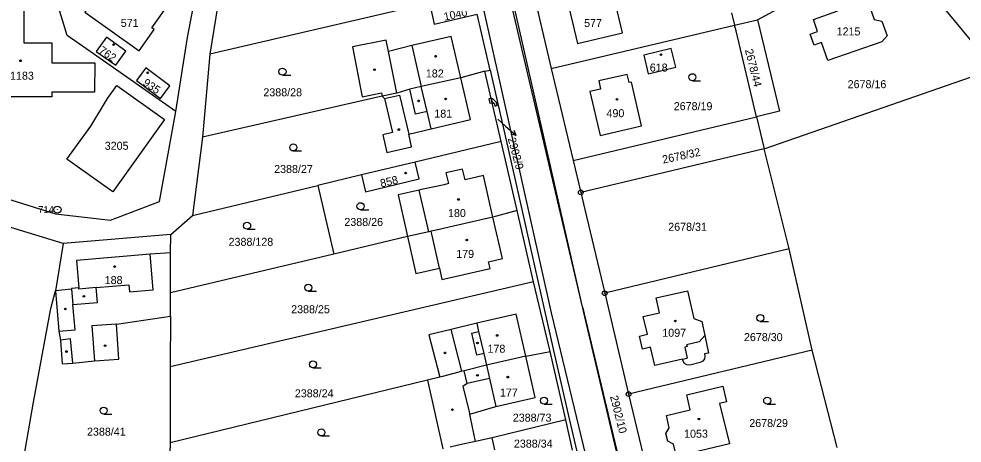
# Model space of a CAD drawing. Extents: x -758836 to -757729, y -1175316 to -1174366.
# Drawn here: x -758454.3 to -758254, y -1175027 to -1174936.9 of the extents above; entities that cross this region are included whole.
import ezdxf

# ---------------------------------------------------------------- set-up
doc = ezdxf.new("R2010")
doc.units = 0
for name, color, linetype in [('Hranice parcel', 7, 'Continuous'), ('Parcelní čísla', 7, 'Continuous'), ('Pop  PČ popisy', 7, 'Continuous'), ('Vnitřní kresba', 7, 'Continuous'), ('Věcná břemena k části', 7, 'Continuous'), ('Značky bodu BP', 7, 'Continuous'), ('Značky budov', 7, 'Continuous'), ('Značky kultur', 7, 'Continuous')]:
    doc.layers.add(name, color=color, linetype=linetype)

msp = doc.modelspace()

# ---------------------------------------------------------------- linework, layer by layer
at = {"layer": 'Hranice parcel'}
for p, q in [((-758345.78, -1174928.06), (-758341.26, -1174947.41)), ((-758357.99, -1174931.4), (-758413.76, -1174944.36)), ((-758354.19, -1174947.79), (-758356.95, -1174935.89)), ((-758302.92, -1174935.57), (-758302.28, -1174938.23)), ((-758302.28, -1174938.23), (-758297.41, -1174937.08)), ((-758341.26, -1174947.41), (-758302.28, -1174938.23)), ((-758413.76, -1174944.36), (-758415.31, -1174962.01)), ((-758355.36, -1174948.01), (-758360.44, -1174949.43)), ((-758355.36, -1174948.01), (-758354.19, -1174947.79)), ((-758351.86, -1174962.91), (-758355.36, -1174948.01)), ((-758341.26, -1174947.41), (-758336.59, -1174966.93)), ((-758377.14, -1174953.27), (-758415.31, -1174962.01)), ((-758336.59, -1174966.93), (-758297.64, -1174957.65)), ((-758297.64, -1174957.65), (-758296.01, -1174964.46)), ((-758415.31, -1174962.01), (-758417.43, -1174978.6)), ((-758351.86, -1174962.91), (-758370.14, -1174967.28)), ((-758348.51, -1174977.6), (-758351.86, -1174962.91)), ((-758296.01, -1174964.46), (-758334.97, -1174973.74)), ((-758290.72, -1174985.7), (-758296.01, -1174964.46)), ((-758336.59, -1174966.93), (-758334.97, -1174973.74)), ((-758370.14, -1174967.28), (-758381.55, -1174970.01)), ((-758360.06, -1174968.77), (-758363.6, -1174969.56)), ((-758381.55, -1174970.01), (-758390.82, -1174972.23)), ((-758417.43, -1174978.6), (-758390.82, -1174972.23)), ((-758390.82, -1174972.23), (-758387.4, -1174986.81)), ((-758422.04, -1174982.66), (-758417.43, -1174978.6)), ((-758348.51, -1174977.6), (-758353.61, -1174978.97)), ((-758345.02, -1174992.7), (-758348.51, -1174977.6)), ((-758422.04, -1174982.66), (-758444.91, -1174984.58)), ((-758371.77, -1174983.1), (-758387.4, -1174986.81)), ((-758444.91, -1174984.58), (-758446.54, -1174994.59)), ((-758387.4, -1174986.81), (-758422.1, -1174995.06)), ((-758290.72, -1174985.7), (-758329.89, -1174995.14)), ((-758285.8, -1175007.25), (-758290.72, -1174985.7)), ((-758345.02, -1174992.7), (-758422.18, -1175010.77)), ((-758341.49, -1175007.47), (-758345.02, -1174992.7)), ((-758422.13, -1175000.03), (-758422.1, -1174995.06)), ((-758329.89, -1174995.14), (-758324.8, -1175016.55)), ((-758422.13, -1175000.03), (-758422.18, -1175010.77)), ((-758346.66, -1175008.52), (-758341.49, -1175007.47)), ((-758338.16, -1175021.98), (-758341.49, -1175007.47)), ((-758285.8, -1175007.25), (-758324.8, -1175016.55)), ((-758280.48, -1175027.85), (-758285.8, -1175007.25)), ((-758422.18, -1175010.77), (-758422.16, -1175026.87)), ((-758364.93, -1175012.95), (-758367.53, -1175013.58)), ((-758367.53, -1175013.58), (-758422.16, -1175026.87)), ((-758367.53, -1175013.58), (-758364.25, -1175028.17)), ((-758324.8, -1175016.55), (-758319.72, -1175037.95)), ((-758336.71, -1175028.44), (-758338.16, -1175021.98)), ((-758422.16, -1175026.87), (-758422.36, -1175032.02))]:
    msp.add_line(p, q, dxfattribs=at)
for points in [[(-758297.14, -1175157.07), (-758301.82, -1175137.17), (-758334.58, -1174998.03), (-758360.35, -1174888.27), (-758361.81, -1174882.07)], [(-758420.99, -1174956.58), (-758418.47, -1174940.81), (-758410.71, -1174900.14)], [(-758297.41, -1174937.08), (-758278.62, -1174926.8), (-758276.96, -1174925.54), (-758269.21, -1174920.77)], [(-758296.01, -1174964.46), (-758247.07, -1174947.51), (-758269.21, -1174920.77)], [(-758410.64, -1174925.24), (-758410.72, -1174925.53), (-758413.76, -1174944.36)], [(-758420.99, -1174956.58), (-758438.47, -1174944.3), (-758444.03, -1174940.39), (-758448.12, -1174927.13)], [(-758422.41, -1174933.59), (-758429.78, -1174928.35), (-758432.94, -1174932.84), (-758436.6, -1174930.22), (-758440.31, -1174935.48), (-758434.92, -1174939.3), (-758428.76, -1174943.67), (-758425.55, -1174939.12), (-758426.06, -1174938.77), (-758422.41, -1174933.59)], [(-758326.1, -1174939.86), (-758328.65, -1174929.09), (-758330.65, -1174929.56), (-758331.04, -1174927.9), (-758337.01, -1174929.38), (-758336.63, -1174930.98), (-758338.22, -1174931.36), (-758335.63, -1174942.14), (-758326.1, -1174939.86)], [(-758460.27, -1174942), (-758460.27, -1174929.65), (-758453.25, -1174929.64), (-758453.27, -1174941.98), (-758447.28, -1174941.99), (-758447.29, -1174946.22), (-758438.2, -1174946.25), (-758438.23, -1174952.48), (-758447.31, -1174952.45), (-758447.31, -1174953.41), (-758466.25, -1174953.42), (-758466.22, -1174942), (-758460.27, -1174942)], [(-758271, -1174941.74), (-758282.48, -1174945.75), (-758283.82, -1174941.92), (-758285.42, -1174942.48), (-758286.25, -1174940.1), (-758284.66, -1174939.55), (-758285.55, -1174937), (-758280.36, -1174935.18), (-758281.59, -1174931.68), (-758275.27, -1174929.47), (-758272.62, -1174937.05), (-758271.01, -1174937.37), (-758269.92, -1174940.49), (-758271, -1174941.74)], [(-758357.84, -1174932.05), (-758366.97, -1174934.14), (-758366.08, -1174938), (-758356.95, -1174935.89)], [(-758297.41, -1174937.08), (-758292.77, -1174956.49), (-758297.64, -1174957.65)], [(-758297.64, -1174957.65), (-758301.99, -1174939.46), (-758302.28, -1174938.23)], [(-758431.62, -1174943.73), (-758435.72, -1174940.79), (-758437.89, -1174943.84), (-758433.72, -1174946.69), (-758431.62, -1174943.73)], [(-758360.44, -1174949.43), (-758362.5, -1174940.61), (-758370.87, -1174942.56), (-758375.84, -1174943.78), (-758376.32, -1174941.41), (-758383.48, -1174942.85), (-758381.37, -1174953.41), (-758377.27, -1174952.58), (-758377.14, -1174953.27)], [(-758321.59, -1174944.61), (-758320.62, -1174948.55), (-758314.79, -1174947.11), (-758315.76, -1174943.17), (-758321.59, -1174944.61)], [(-758424.22, -1174953.77), (-758422.22, -1174951.09), (-758427.35, -1174947.26), (-758429.34, -1174949.94), (-758424.22, -1174953.77)], [(-758354.19, -1174947.79), (-758350.83, -1174962.63), (-758347.5, -1174977.35), (-758344.08, -1174992.47), (-758340.74, -1175007.26), (-758337.45, -1175021.81), (-758333.96, -1175036.62)], [(-758330.75, -1174951.82), (-758333.01, -1174952.34), (-758330.83, -1174961.64), (-758322.1, -1174959.62), (-758324.21, -1174950.31), (-758324.7, -1174950.42), (-758325.1, -1174948.69), (-758331.15, -1174950.07), (-758330.75, -1174951.82)], [(-758444.11, -1174966.68), (-758439.05, -1174959.65), (-758435.5, -1174953.79), (-758433.5, -1174951.03), (-758423.38, -1174958.27), (-758429.38, -1174966.65), (-758434.39, -1174973.64), (-758444.11, -1174966.68)], [(-758360.44, -1174949.43), (-758368.84, -1174951.27), (-758371.27, -1174951.84), (-758374.07, -1174952.64), (-758377.14, -1174953.27)], [(-758377.14, -1174953.27), (-758376.62, -1174953.8), (-758374.94, -1174961.04), (-758377.02, -1174961.53), (-758376.15, -1174965.26), (-758370.9, -1174964.04), (-758371.52, -1174961.37), (-758366.75, -1174960.25), (-758358.38, -1174958.26), (-758360.44, -1174949.43)], [(-758484.1, -1174965.51), (-758456.91, -1174975), (-758446.51, -1174978.25), (-758434.83, -1174979.65), (-758424.43, -1174975.65), (-758423.87, -1174972.53), (-758420.99, -1174956.58)], [(-758381.55, -1174970.01), (-758380.69, -1174973.59), (-758369.29, -1174970.86), (-758370.14, -1174967.28)], [(-758353.61, -1174978.97), (-758355.65, -1174970.15), (-758359.51, -1174971.04), (-758360.06, -1174968.77)], [(-758363.6, -1174969.56), (-758363.08, -1174971.87), (-758364.01, -1174972.09), (-758368.78, -1174973.13), (-758369.28, -1174973.24), (-758373.76, -1174974.24), (-758371.77, -1174983.1)], [(-758444.91, -1174984.58), (-758455.08, -1174981.44), (-758479.07, -1174974.04)], [(-758334.97, -1174973.74), (-758334.1, -1174977.34), (-758329.89, -1174995.14)], [(-758353.61, -1174978.97), (-758361.97, -1174980.89), (-758365.3, -1174981.64), (-758366.74, -1174981.96), (-758367.27, -1174982.08), (-758371.77, -1174983.1)], [(-758371.77, -1174983.1), (-758370.01, -1174990.93), (-758364.99, -1174989.81), (-758364.46, -1174992.19), (-758354.23, -1174989.91), (-758354.56, -1174988.45), (-758351.58, -1174987.79), (-758353.61, -1174978.97)], [(-758422.1, -1174995.06), (-758422.13, -1174986.59), (-758422.04, -1174982.66)], [(-758454.79, -1175039.02), (-758451.2, -1175018.23), (-758447.49, -1174998.37), (-758446.54, -1174994.59)], [(-758446.54, -1174994.59), (-758445.82, -1175003.19), (-758445.5, -1175005.08), (-758445.13, -1175010.09), (-758442.86, -1175009.98), (-758438.26, -1175009.5), (-758433.06, -1175009.14), (-758433.61, -1175001.68), (-758422.13, -1175000.03)], [(-758309.03, -1175009.57), (-758309.58, -1175009.85), (-758311.78, -1175010.37), (-758312.46, -1175010.32), (-758312.95, -1175010.02), (-758313.23, -1175009.55), (-758313.37, -1175009.14), (-758319.26, -1175010.49), (-758320.17, -1175006.61), (-758321.86, -1175007.01), (-758322.51, -1175004.23), (-758320.82, -1175003.84), (-758321.7, -1175000.08), (-758318.23, -1174999.29), (-758318.95, -1174996.13), (-758312.28, -1174994.61), (-758310.94, -1175000.51), (-758309.26, -1175001.14), (-758308.6, -1175004.09), (-758307.86, -1175007.86), (-758308.69, -1175008.03), (-758308.6, -1175008.49), (-758308.68, -1175009.03), (-758309.03, -1175009.57)], [(-758346.66, -1175008.52), (-758348.71, -1174999.57), (-758357.07, -1175001.48), (-758362.52, -1175002.8), (-758367.25, -1175003.97), (-758364.93, -1175012.95)], [(-758346.66, -1175008.52), (-758355.01, -1175010.43), (-758359.72, -1175011.59), (-758360.2, -1175011.71), (-758360.88, -1175011.88), (-758364.33, -1175012.8), (-758364.93, -1175012.95)], [(-758357.3, -1175026.59), (-758358.38, -1175021.51), (-758358.56, -1175020.81), (-758353, -1175019.16), (-758344.66, -1175017.24), (-758346.66, -1175008.52)], [(-758316.49, -1175026.54), (-758316.87, -1175024.92), (-758316.16, -1175023.7), (-758316.76, -1175021.06), (-758311.73, -1175019.86), (-758312.45, -1175016.67), (-758304.82, -1175014.83), (-758304.04, -1175018.21), (-758305.51, -1175018.52), (-758303.4, -1175027.1), (-758314.6, -1175029.81), (-758315.26, -1175027.2), (-758316.49, -1175026.54)], [(-758338.16, -1175021.98), (-758353.81, -1175025.81), (-758357.3, -1175026.59)], [(-758357.3, -1175026.59), (-758360.67, -1175027.34), (-758362.74, -1175027.81)]]:
    msp.add_lwpolyline(points, dxfattribs=at)
at = {"layer": 'Pop  PČ popisy'}
for p, q in [((-758352.6, -1174958.15), (-758350.94, -1174959.64)), ((-758350.94, -1174959.64), (-758348.71, -1174961.65)), ((-758348.71, -1174961.65), (-758349.12, -1174960.61)), ((-758348.71, -1174961.65), (-758349.79, -1174961.35))]:
    msp.add_line(p, q, dxfattribs=at)
at = {"layer": 'Vnitřní kresba'}
for p, q in [((-758334.58, -1174998.03), (-758355.8, -1174904.75)), ((-758341.2, -1174999.31), (-758361.89, -1174906.28)), ((-758370.87, -1174942.56), (-758368.84, -1174951.27)), ((-758374.07, -1174952.64), (-758375.84, -1174943.78)), ((-758376.62, -1174953.8), (-758373.45, -1174953.06)), ((-758373.45, -1174953.06), (-758371.52, -1174961.37)), ((-758370.04, -1174957.12), (-758371.27, -1174951.84)), ((-758367.61, -1174956.55), (-758368.84, -1174951.27)), ((-758367.61, -1174956.55), (-758370.04, -1174957.12)), ((-758366.75, -1174960.25), (-758367.61, -1174956.55)), ((-758367.27, -1174982.08), (-758369.28, -1174973.24)), ((-758364.99, -1174989.81), (-758366.74, -1174981.96)), ((-758426.41, -1174986.84), (-758442.07, -1174988.17)), ((-758422.13, -1174986.59), (-758426.41, -1174986.84)), ((-758425.76, -1174994.43), (-758426.41, -1174986.84)), ((-758442.07, -1174988.17), (-758441.58, -1174994.02)), ((-758443.15, -1174994.3), (-758446.54, -1174994.59)), ((-758441.58, -1174994.02), (-758443.16, -1174994.15)), ((-758443.16, -1174994.15), (-758443.15, -1174994.3)), ((-758443.15, -1174994.3), (-758442.85, -1174997.56)), ((-758441.56, -1174994.25), (-758441.58, -1174994.02)), ((-758437.9, -1174993.94), (-758441.56, -1174994.25)), ((-758437.9, -1174993.94), (-758430.93, -1174993.35)), ((-758437.62, -1174997.12), (-758437.9, -1174993.94)), ((-758430.93, -1174993.35), (-758430.81, -1174994.86)), ((-758430.81, -1174994.86), (-758425.76, -1174994.43)), ((-758442.85, -1174997.56), (-758437.62, -1174997.12)), ((-758442.39, -1175002.9), (-758442.85, -1174997.56)), ((-758334.58, -1174998.03), (-758301.51, -1175137.25)), ((-758303.3, -1175156.35), (-758341.2, -1174999.31)), ((-758445.82, -1175003.19), (-758442.39, -1175002.9)), ((-758433.61, -1175001.68), (-758438.79, -1175002.08)), ((-758438.79, -1175002.08), (-758438.26, -1175009.5)), ((-758360.2, -1175011.71), (-758362.52, -1175002.8)), ((-758357.07, -1175001.48), (-758356.66, -1175003.25)), ((-758443.34, -1175004.79), (-758445.5, -1175005.08)), ((-758442.86, -1175009.98), (-758443.34, -1175004.79)), ((-758358.12, -1175003.59), (-758356.66, -1175003.25)), ((-758357.05, -1175008.27), (-758358.12, -1175003.59)), ((-758356.66, -1175003.25), (-758355.58, -1175007.93)), ((-758309.82, -1175005.44), (-758308.6, -1175004.09)), ((-758312.38, -1175006.45), (-758312.89, -1175006.58)), ((-758312.89, -1175006.58), (-758312.35, -1175008.9)), ((-758309.82, -1175005.44), (-758312.52, -1175006.11)), ((-758312.52, -1175006.11), (-758312.38, -1175006.45)), ((-758355.58, -1175007.93), (-758357.05, -1175008.27)), ((-758355.58, -1175007.93), (-758355.01, -1175010.43)), ((-758313.37, -1175009.14), (-758312.35, -1175008.9)), ((-758355.01, -1175010.43), (-758354.37, -1175013.21)), ((-758359.08, -1175014.29), (-758359.72, -1175011.59)), ((-758354.37, -1175013.21), (-758359.08, -1175014.29)), ((-758354.37, -1175013.21), (-758353, -1175019.16)), ((-758359.08, -1175014.29), (-758360.03, -1175014.91)), ((-758360.03, -1175014.91), (-758358.56, -1175020.81)), ((-758353.24, -1175028.35), (-758353.81, -1175025.81))]:
    msp.add_line(p, q, dxfattribs=at)
at = {"layer": 'Věcná břemena k části'}
for points in [[(-758354.28, -1174954.81), (-758353.79, -1174954.69), (-758353.85, -1174954.45), (-758354.02, -1174953.72), (-758354.51, -1174953.84)], [(-758354.02, -1174953.72), (-758353.85, -1174954.45), (-758353.3, -1174954.91), (-758353.23, -1174955.39), (-758352.73, -1174955.31), (-758352.84, -1174954.67), (-758353.62, -1174953.88)]]:
    msp.add_lwpolyline(points, close=True, dxfattribs=at)
at = {"layer": 'Značky bodu BP'}
for centre, radius in [((-758334.97, -1174973.74), 0.5), ((-758334.97, -1174973.74), 0.0303), ((-758446.11, -1174977.38), 0.75), ((-758446.11, -1174977.38), 0.03), ((-758329.89, -1174995.14), 0.5), ((-758329.89, -1174995.14), 0.0303), ((-758324.8, -1175016.55), 0.5), ((-758324.8, -1175016.55), 0.0303)]:
    msp.add_circle(centre, radius, dxfattribs=at)
at = {"layer": 'Značky budov'}
for centre in [(-758434.17, -1174942.33), (-758365.8, -1174944.82), (-758317.92, -1174944.5), (-758453.97, -1174945.78), (-758426.94, -1174948.34), (-758378.78, -1174947.66), (-758369.38, -1174954.3), (-758363.68, -1174953.87), (-758327.26, -1174953.96), (-758373.62, -1174960.38), (-758372.17, -1174969.63), (-758360.94, -1174975.23), (-758359.18, -1174983.84), (-758433.96, -1174989.47), (-758440.5, -1174995.79), (-758444.43, -1174998.48), (-758314.88, -1175001.02), (-758352.71, -1175004.09), (-758436, -1175006.25), (-758356.91, -1175005.69), (-758444.19, -1175007.52), (-758363.79, -1175007.79), (-758356.91, -1175012.56), (-758350.45, -1175012.94), (-758362.24, -1175019.85), (-758309.88, -1175021.85)]:
    msp.add_circle(centre, 0.175, dxfattribs=at)
at = {"layer": 'Značky kultur'}
for p, q in [((-758398.32, -1174948.84), (-758396.57, -1174948.84)), ((-758311.26, -1174950.02), (-758309.51, -1174950.02)), ((-758396.03, -1174964.93), (-758394.28, -1174964.93)), ((-758381.75, -1174977.41), (-758380, -1174977.41)), ((-758405.84, -1174981.54), (-758404.09, -1174981.54)), ((-758392.84, -1174994.7), (-758391.09, -1174994.7)), ((-758296.84, -1175001.15), (-758295.09, -1175001.15)), ((-758391.85, -1175010.98), (-758390.1, -1175010.98)), ((-758342.76, -1175018.69), (-758341.01, -1175018.69)), ((-758295.36, -1175018.69), (-758293.61, -1175018.69)), ((-758436.3, -1175020.8), (-758434.55, -1175020.8)), ((-758390.06, -1175025.44), (-758388.31, -1175025.44))]:
    msp.add_line(p, q, dxfattribs=at)
for centre in [(-758398.32, -1174948.09), (-758311.26, -1174949.27), (-758396.03, -1174964.18), (-758381.75, -1174976.66), (-758405.84, -1174980.79), (-758392.84, -1174993.95), (-758296.84, -1175000.4), (-758391.85, -1175010.23), (-758342.76, -1175017.94), (-758295.36, -1175017.94), (-758436.3, -1175020.05), (-758390.06, -1175024.69)]:
    msp.add_circle(centre, 0.75, dxfattribs=at)

# ---------------------------------------------------------------- texts
at = {"layer": 'Parcelní čísla'}
for s, rotation, p in [('1040', 12, (-758363.88, -1174937.29)), ('762', 326, (-758437.5, -1174943.97)), ('2678/44', 284, (-758300.11, -1174943.5)), ('935', 326, (-758428.13, -1174950.83)), ('2902/9', 285, (-758350.48, -1174962.32)), ('2678/32', 12, (-758317.45, -1174967.62)), ('858', 13, (-758377.35, -1174972.67)), ('2902/10', 284, (-758328.76, -1175017.05))]:
    msp.add_text(s, height=1.7, rotation=rotation, dxfattribs=at).set_placement(p)
for s, p in [('571', (-758432.67, -1174938.6)), ('577', (-758334.26, -1174938.62)), ('1215', (-758280.63, -1174940.41)), ('618', (-758320.31, -1174948.08)), ('1183', (-758456.19, -1174949.81)), ('182', (-758367.87, -1174949.33)), ('2678/16', (-758278.28, -1174951.6)), ('2388/28', (-758402.38, -1174953.32)), ('2678/19', (-758315.22, -1174956.27)), ('181', (-758366.08, -1174957.86)), ('490', (-758329.5, -1174957.76)), ('3205', (-758436.08, -1174964.68)), ('2388/27', (-758400.09, -1174969.61)), ('2388/26', (-758385.18, -1174980.85)), ('180', (-758363.16, -1174978.96)), ('2678/31', (-758316.39, -1174981.88)), ('2388/128', (-758409.77, -1174985.07)), ('179', (-758361.42, -1174987.63)), ('188', (-758436.09, -1174993.19)), ('2388/25', (-758396.48, -1174999.38)), ('1097', (-758317.65, -1175004.38)), ('2678/30', (-758300.31, -1175005.3)), ('178', (-758354.78, -1175007.76)), ('2388/24', (-758395.7, -1175017.23)), ('177', (-758352.15, -1175017.08)), ('2388/73', (-758349.41, -1175022.4)), ('2678/29', (-758299.18, -1175023.54)), ('2388/41', (-758439.84, -1175025.38)), ('1053', (-758313.02, -1175025.81)), ('2388/34', (-758349.17, -1175027.91))]:
    msp.add_text(s, height=1.7, dxfattribs=at).set_placement(p)
at = {"layer": 'Značky bodu BP'}
msp.add_text('714', height=1.5, dxfattribs=at).set_placement((-758450.21, -1174978.13))

doc.saveas('drawing.dxf')
